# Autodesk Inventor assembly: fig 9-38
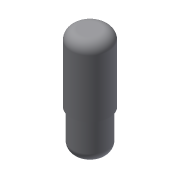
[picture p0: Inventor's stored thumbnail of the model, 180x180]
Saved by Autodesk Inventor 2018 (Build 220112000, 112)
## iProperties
Created: 2013-07
Part Number: fig 9-38
Document SubType Name: Assembly
Designer: CADCIM
Author: CADCIM
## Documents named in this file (3)
- E:\_Deepak\Inventor\Autodesk Inventor_2017_Project\Resources\Inventor_2018_Part\c09_Inv_2018\c09_inv_2018_prt\fig 9-38.iam
- E:\_Deepak\Inventor\Autodesk Inventor_2017_Project\Resources\Inventor_2018_Part\c09_Inv_2018\c09_inv_2018_prt\10.ipt
- E:\_Deepak\Inventor\Autodesk Inventor_2017_Project\Resources\Inventor_2018_Part\c09_Inv_2018\c09_inv_2018_prt\11.ipt
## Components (2 placed, 2 different names)
1. 10:1 — Rigid:1
2. 11:1 — Rigid:1
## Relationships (1: WeldJoint 1)
- Rigid:1 [WeldJoint]: 10:1 ↔ 11:1
